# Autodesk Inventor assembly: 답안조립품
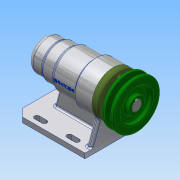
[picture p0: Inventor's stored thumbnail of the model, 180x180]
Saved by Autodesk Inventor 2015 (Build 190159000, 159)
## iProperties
Created: 2017-09
Part Number: 답안조립품
Document SubType Name: Assembly
Designer: owner
Author: owner
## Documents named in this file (11)
- C:\Users\owner\Desktop\470907V1016\답안조립품.iam
- C:\Users\owner\Desktop\470907V1016\본체.ipt
- C:\Users\owner\Desktop\470907V1016\베어링 51202.ipt
- C:\Users\owner\Desktop\470907V1016\어댑터슬리브.ipt
- C:\Users\owner\Desktop\470907V1016\축.ipt
- C:\Users\owner\Desktop\470907V1016\베어링 6004.ipt
- C:\Users\owner\Desktop\470907V1016\볼트 M4 x 12.ipt
- C:\Users\owner\Desktop\470907V1016\커버.ipt
- C:\Users\owner\Desktop\470907V1016\키 5 x 5 x 16.ipt
- C:\Users\owner\Desktop\470907V1016\V벨트풀리.ipt
- C:\Users\owner\Desktop\470907V1016\멈춤나사 M3x8.ipt
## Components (1 placed, 1 different names)
1. V벨트풀리:1 — 각도:2
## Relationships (1: Angle 1)
- 각도:2 [Angle]: V벨트풀리:1
